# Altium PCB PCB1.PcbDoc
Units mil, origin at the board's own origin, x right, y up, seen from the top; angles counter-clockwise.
Board outline 6000 x 4000 mil, 2 copper layers (Top Layer, Bottom Layer); 38 components, 42 nets, 169 pads, 9 vias.
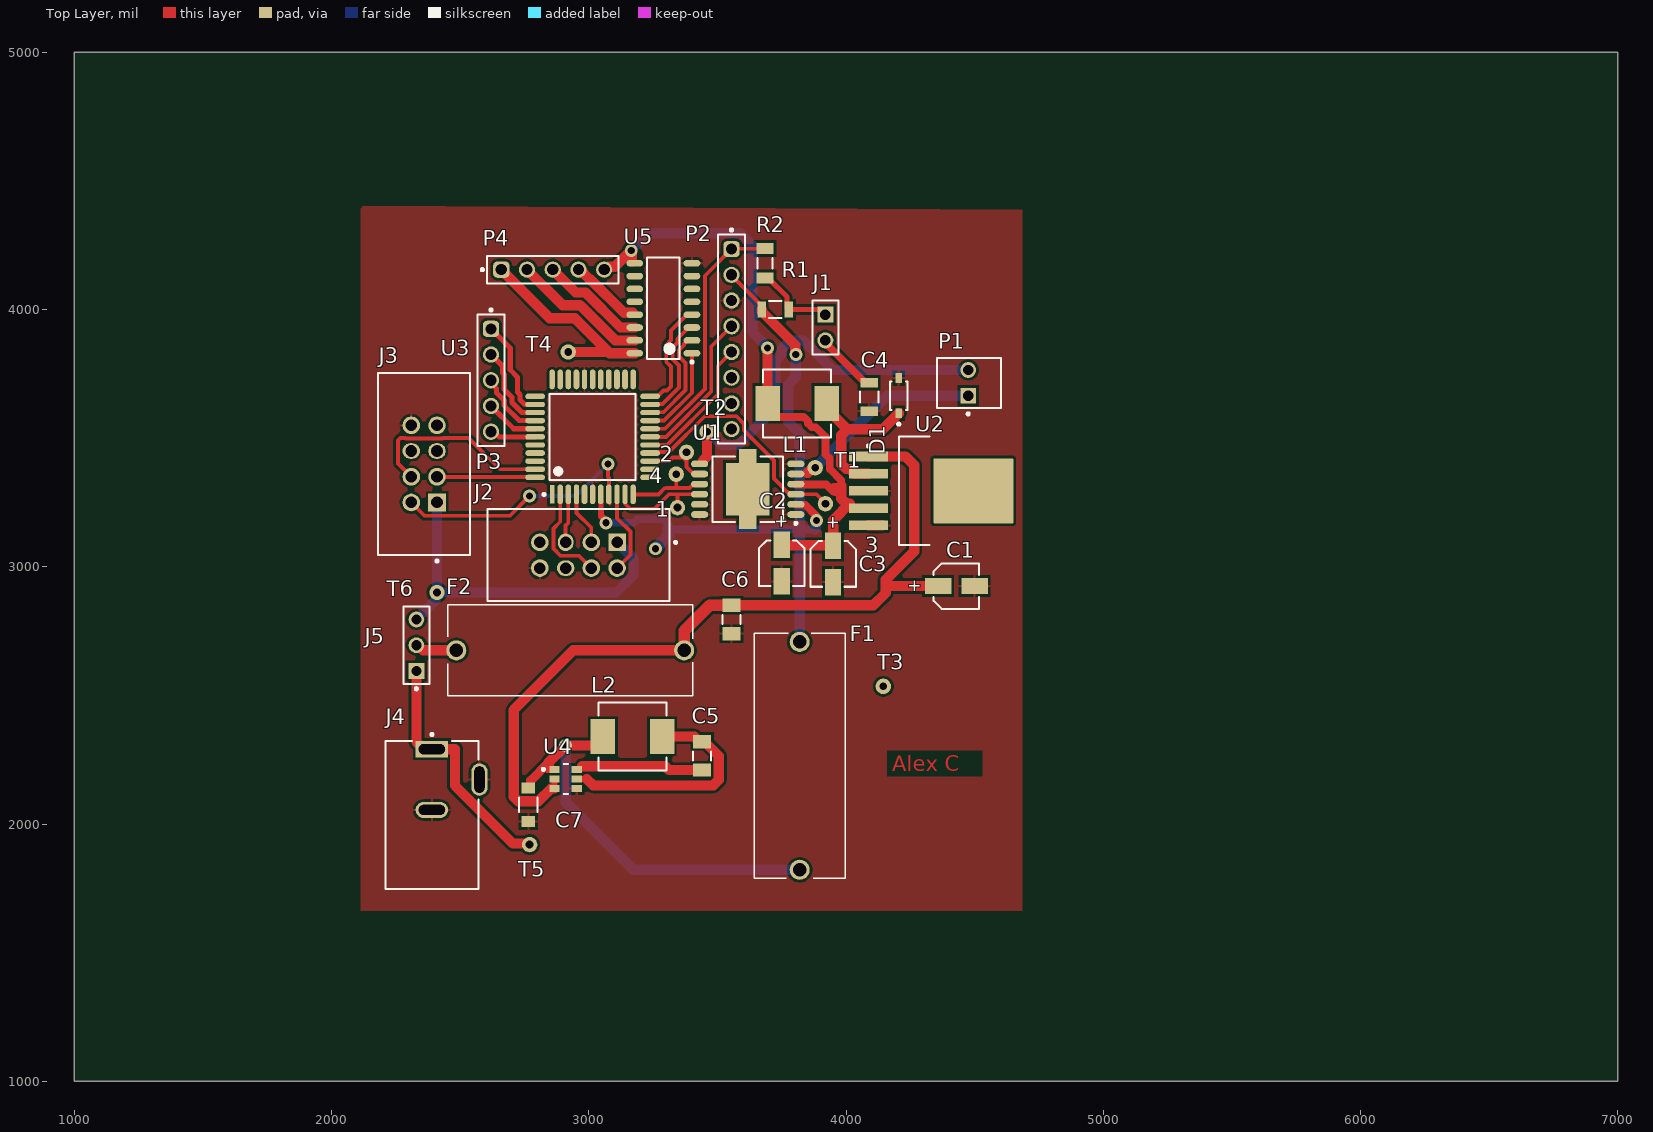
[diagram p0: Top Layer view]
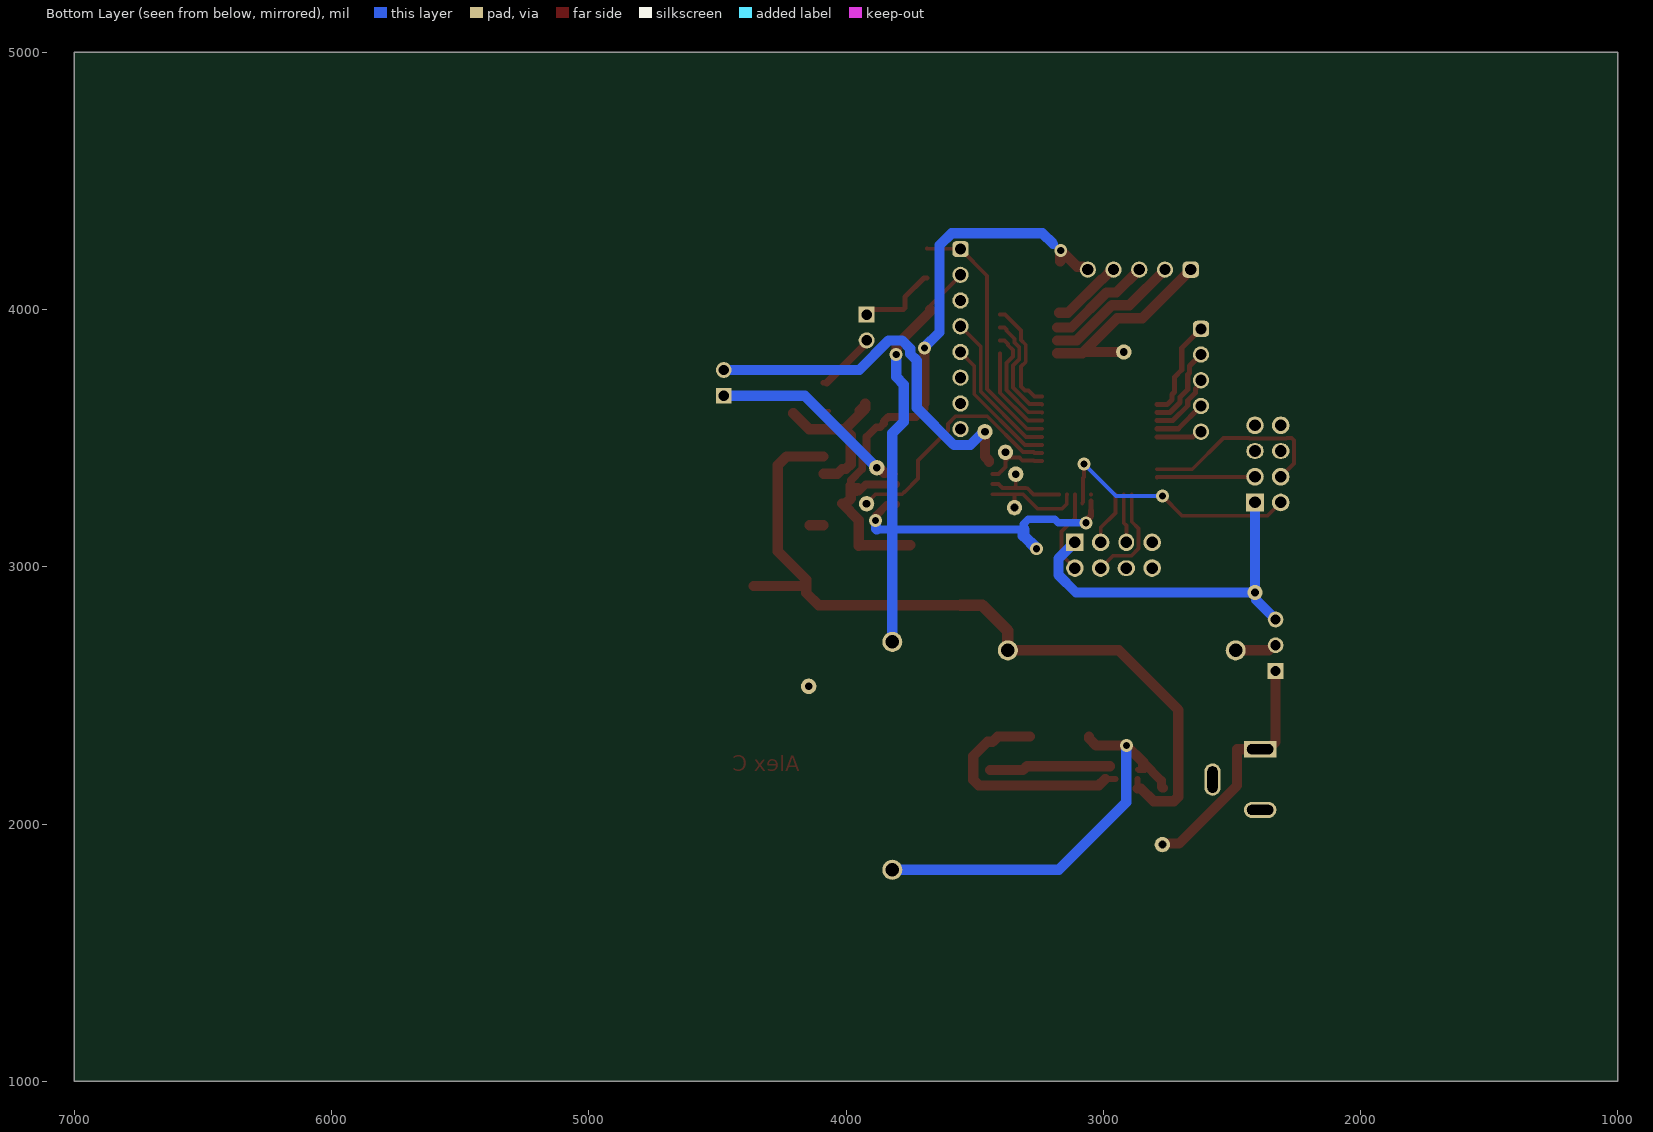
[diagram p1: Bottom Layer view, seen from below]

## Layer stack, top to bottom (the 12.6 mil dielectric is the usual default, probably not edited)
Top Solder: solder mask 0.4, Solder Resist, Dk 3.5
Top Layer: signal copper 1.4
Dielectric 1: dielectric 12.6, FR-4, Dk 4.8
Bottom Layer: signal copper 1.4
Bottom Solder: solder mask 0.4, Solder Resist, Dk 3.5

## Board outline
1000,1000 7000,1000 7000,5000 1000,5000

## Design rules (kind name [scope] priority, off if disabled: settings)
Clearance [All] p1: gap=10 ignorepadtopadclearanceinfootprint=FALSE
HoleSize [All] p1: absolutevalues=TRUE maxlimit=100 minlimit=20 maxpercent=80.000 minpercent=20.000
HoleToHoleClearance [All] p1: gap=17.72 allowstackedmicrovias=TRUE
MinimumAnnularRing [All] p1: minimumring=9.84
MinimumSolderMaskSliver [All] p1: minsoldermaskwidth=7.87
PolygonConnect [All] p1: connectstyle=Relief reliefconductorwidth=10 reliefentries=4 polygonreliefangle="90 Angle" airgapwidth=10
RoutingVias [All] p1: holewidth=28 width=50 viastyle="Through Hole" minholewidth=28 minwidth=50 maxholewidth=28 maxwidth=50
SilkToSilkClearance [All] p1: silktosilkclearance=9
SilkToSolderMaskClearance [IsPad] p1: minsilkscreentomaskgap=5.91 clearancetoexposedcopper=TRUE
SolderMaskExpansion [All] p1: expansion=4 istentingtop=FALSE
SupplyNets "Schematic Supply Nets_3" [InNet('GND')] p1: voltage=0.000
SupplyNets "Schematic Supply Nets_2" [InNet('+5')] p2: voltage=0.000
SupplyNets "Schematic Supply Nets_1" [InNet('+12')] p3: voltage=0.000
SupplyNets "Schematic Supply Nets" [InNet('+3.3')] p4: voltage=0.000
Width [All] p1: maxlimit=50 minlimit=15 preferedwidth=40 minimp=50.000000 maximp=50.000000 favimp=50.000000
25 further rules are at their usual default settings.

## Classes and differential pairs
component class Sheet1: 1 2 3 4 C1 C2 C6 D1 F1 F2 J1 J2 J3 J4 J5 L1 L2 M P4 R1 R2 T1 T2 T3 U1 U2 U3 U4 U5

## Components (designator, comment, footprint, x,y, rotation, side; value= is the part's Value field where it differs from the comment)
1 "Test point" "Test point-Footprint-1" 3345,3230 r90 top
2 "Test point" "Test point-Footprint-1" 3380,3445 r90 top
3 "Test point" "Test point-Footprint-1" 3920,3245 r90 top
4 "Test point" "Test point-Footprint-1" 3340,3360 r90 top
C1 "100uf" WCAP-AS5H_D4H5.5 -45570.87,-47075 r180 top
C2 "300uf" WCAP-AS5H_D4H5.5 -46250,53014.13 r90 top
C3 "100uf" WCAP-AS5H_D4H5.5 -46050,53010.87 r90 top
C4 "0.1uF 25V" FP-C1206C-EB-MFG 4090,3660 r270 top value=100nF
C5 "" FP-1206-L_3_2_0_2-W_1_6_0-IPC_B 3440,2265 r90 top value=100nF
C6 "10uF" FP-1206-L_3_2_0_2-W_1_6_0-IPC_B 3555,2795 r270 top value=100nF
C7 "2x22uF" FP-C3216-160-0_2-MFG 2765,2075 r270 top value=22uF
D1 "1N5819" FP-SOD-123-MFG 4205,3665 r90 top
F1 "4628" FUSE_4628 3820,2265 r90 top
F2 "1.5A" FUSE_4628 2927.91,2675 r0 top
J1 "Conn 01x02" 90120-0762-Footprint-1 3920,3930 r270 top
J2 "Conn 02x04" FP-0702460801-MFG#1 2960,3045 r180 top
J3 "Conn 02x04" FP-0702460801-MFG#2 2360,3400 r90 top
J4 "PJ-102A" FP-PJ-102A-MFG 2390,2035 r180 top
J5 "Conn 01x03" FP-90120-0123-MFG 2330,2695 r90 top
L1 "300 uh" FP-IHLP-2525EZ-FP_2_413x3-MFG 3810,3635 r180 top
L2 "4.7uH" FP-IHLP-2525EZ-FP_2_413x3-MFG 3170,2340 r180 top
P1 "22-23-2021" MOLX-22-23-2021_V 4475,3715 r90 top
P2 "Conn 01x08" 61300811121 3555,3885 r270 top
P3 "BreaKout Headers" 61300511121 2620,3725 r270 top
P4 "Stepper Motor Headers" 61300511121 2860,4155 r0 top
R1 "10k 0.25w" FP-CR1206-IPC_C 3725,4000 r0 top value=10kR
R2 "220 0.25w" RESC3216X60X45NL10T20 3685,4180 r90 top value=220R
T1 "Test point" "Test point-Footprint-1" 3880,3385 r0 top
T2 "Test point" "Test point-Footprint-1" 3460,3525 r0 top
T3 "" "Test point-Footprint-1" 4145,2535 r0 top
T4 "Test point" "Test point-Footprint-1" 2920,3835 r0 top
T5 "Test point" "Test point-Footprint-1" 2770,1920 r90 top
T6 "Test point" "Test point-Footprint-1" 2410,2900 r90 top
U1 "IFX9201SGAUMA1" INF-PG-DSO-12-17_L 3617.99,3301.57 r180 top
U2 "LM2575SX-5.0/NOPB" KTT0005B_L 4331.61,3295 r0 top
U3 "PIC18F47Q10-I/PT" FP-C04-076-IPC_A 3015,3505 r90 top
U4 "AP63203WU-7" FP-TSOT26-MFG 2910,2175 r0 top
U5 "ULN2003D1013TR" STM-SO-16_M 3290,4005 r180 top

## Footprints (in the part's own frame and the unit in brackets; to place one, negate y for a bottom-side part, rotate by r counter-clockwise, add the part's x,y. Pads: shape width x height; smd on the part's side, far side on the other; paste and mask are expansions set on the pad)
90120-0762-Footprint-1 [mm]
  rect 1.57x1.57 hole 1.02 paste-2539.97 mask+0: 1(-1.27,-0.004)
  round 1.57 hole 1.02 paste-2539.97 mask+0: 2(1.27,-0.004)
  silkscreen extent -2.67,-1.27 2.67,1.27, body extent -2.79,-1.44 2.79,1.4, height 0.25
61300511121 [mm] "Pin Header, pitch 2.54 mm, THT, Vertical, single row, 5p"
  rrect50% 1.6x1.6 hole 1.1: 1(-5.08,0)
  round 1.6 hole 1.1: 2(-2.54,0) 3(0,0) 4(2.54,0) 5(5.08,0)
  silkscreen extent -7.07,-1.34 6.5,1.34, body extent -6.35,-1.27 6.35,1.27, height 8.57
61300811121 [mm] "Pin Header, pitch 2.54 mm, THT, Vertical, single row, 8p"
  rrect50% 1.6x1.6 hole 1.1: 1(-8.89,0)
  round 1.6 hole 1.1: 2(-6.35,0) 3(-3.81,0) 4(-1.27,0) 5(1.27,0) 6(3.81,0) 7(6.35,0) 8(8.89,0)
  silkscreen extent -10.88,-1.34 10.31,1.34, body extent -10.16,-1.27 10.16,1.27, height 8.57
FP-1206-L_3_2_0_2-W_1_6_0-IPC_B [mil]
  rect 51.36x71.11 smd paste+0 mask+0: 1(-55.15,0) 2(55.15,0)
  silkscreen extent -18,-36 18,36, body extent -91,-45 91,45, height 10
FP-90120-0123-MFG [mm]
  rect 1.55x1.55 hole 1 paste-2539.97 mask+0: 1(-2.54,0)
  round 1.55 hole 1 paste-2539.97 mask+0: 2(0,0) 3(2.54,0)
  silkscreen extent -4.42,-1.27 3.81,1.27, body extent -3.91,-1.37 3.91,1.37, height 0.25
FP-0702460801-MFG#1 [mm]
  rect 1.74x1.74 hole 1.14 paste-2539.97 mask+0: 1(-3.81,-1.27)
  round 1.74 hole 1.14 paste-2539.97 mask+0: 2(-3.81,1.27) 3(-1.27,-1.27) 4(-1.27,1.27) 7(3.81,-1.27) 8(3.81,1.27)
  oval 1.537x1.74 hole 1.14 paste-2539.97 mask+0: 5(1.27,-1.27)
  oval 1.74x1.537 hole 1.14 paste-2539.97 mask+0: 6(1.27,1.27)
  silkscreen extent -9.72,-4.54 8.99,4.54, body extent -9.09,-4.64 9.09,4.64, height 0.25
FP-0702460801-MFG#2 [mm]
  rect 1.74x1.74 hole 1.14 paste-2539.97 mask+0: 1(-3.81,-1.27)
  round 1.74 hole 1.14 paste-2539.97 mask+0: 2(-3.81,1.27) 3(-1.27,-1.27) 4(-1.27,1.27) 7(3.81,-1.27) 8(3.81,1.27)
  oval 1.537x1.74 hole 1.14 paste-2539.97 mask+0: 5(1.27,-1.27) 6(1.27,1.27)
  silkscreen extent -9.71,-4.54 8.99,4.54, body extent -9.09,-4.64 9.09,4.64, height 0.25
FP-C04-076-IPC_A [mm]
  rect 1.803x0.464 smd paste+0 mask+0: 1(-5.675,4)
  rrect100% 1.955x0.526 smd paste+0 mask+0: 2(-5.675,3.2) 3(-5.675,2.4) 4(-5.675,1.6) 6(-5.675,0) 7(-5.675,-0.8) 8(-5.675,-1.6) 9(-5.675,-2.4) 10(-5.675,-3.2) 11(-5.675,-4) 27(5.675,-0.8) 29(5.675,0.8) 31(5.675,2.4) 33(5.675,4)
  rrect100% 1.955x0.566 smd paste+0 mask+0: 5(-5.675,0.8) 23(5.675,-4) 24(5.675,-3.2) 25(5.675,-2.4) 26(5.675,-1.6) 28(5.675,0) 30(5.675,1.6)
  rrect100% 0.566x1.955 smd paste+0 mask+0: 12(-4,-5.675) 13(-3.2,-5.675) 15(-1.6,-5.675) 17(0,-5.675) 22(4,-5.675) 34(4,5.675) 39(0,5.675) 41(-1.6,5.675) 43(-3.2,5.675)
  rrect100% 0.526x1.955 smd paste+0 mask+0: 14(-2.4,-5.675) 16(-0.8,-5.675) 18(0.8,-5.675) 19(1.6,-5.675) 20(2.4,-5.675) 21(3.2,-5.675) 35(3.2,5.675) 36(2.4,5.675) 37(1.6,5.675) 38(0.8,5.675) 40(-0.8,5.675) 42(-2.4,5.675) 44(-4,5.675)
  rrect100% 1.953x0.526 smd paste+0 mask+0: 32(5.675,3.2)
  silkscreen extent -5.8,-4.25 4.25,4.92, body extent -7.15,-7.15 7.15,7.15, height 0.25
FP-C1206C-EB-MFG [mm]
  rect 0.95x1.7 smd paste+0 mask+0: 1(-1.4,0) 2(1.4,0)
  silkscreen extent -0.55,-0.9 0.55,0.9, body extent -2,-1 2,1, height 0.25
FP-C3216-160-0_2-MFG [mm]
  rect 1.1x1.35 smd paste+0 mask+0: 1(-1.65,0) 2(1.65,0)
  silkscreen extent -0.72,-0.9 0.72,0.9, body extent -2.3,-1 2.3,1, height 0.25
FP-CR1206-IPC_C [mil]
  rect 33.79x61.5 smd paste+0 mask+0: 1(-52.24,0) 2(52.24,0)
  silkscreen extent -24,-32 24,32, body extent -73,-36 73,36, height 10
FP-IHLP-2525EZ-FP_2_413x3-MFG [mil]
  rect 95x135 smd paste+0 mask+0: 1(-115,0) 2(115,0)
  silkscreen extent -132,-132 132,132, body extent -166,-136 166,136, height 10
FP-PJ-102A-MFG [mm]
  rect 3.2x1.6 hole 1 slot 2.6 at 0 deg paste-2539.97 mask+0: 1(0,-6.5)
  rrect100% 3.2x1.6 hole 1 slot 2.6 at 0 deg paste-2539.97 mask+0: 2(0,-0.5)
  rrect100% 1.6x3.2 hole 2.6 slot 1 at 0 deg paste-2539.97 mask+0: 3(-4.7,-3.5)
  silkscreen extent -4.6,-8.07 4.6,7.3, body extent -5.6,-7.4 4.7,7.4, height 0.25
FP-SOD-123-MFG [mm]
  rect 0.97x0.65 smd paste+0 mask+0: 1(-1.74,0) 2(1.74,0)
  silkscreen extent -2.92,-0.85 1.42,0.85, body extent -2.32,-0.95 2.32,0.95, height 0.25
FP-TSOT26-MFG [mm]
  rect 1x0.7 smd paste+0 mask+0: 1(-1.099,0.95) 3(-1.099,-0.95) 4(1.099,-0.95) 6(1.099,0.95)
  rect 1x0.687 smd paste+0 mask+0: 2(-1.099,0) 5(1.099,0)
  silkscreen extent -2.32,-1.5 0.22,1.5, body extent -1.7,-1.6 1.7,1.6, height 0.25
FUSE_4628 [mm]
  round 1.98 hole 1.32: 1(-11.25,0) 2(11.25,0)
  silkscreen extent -12.1,-4.49 12.1,4.49, body extent -12.1,-4.5 12.1,4.5, height 11.99
INF-PG-DSO-12-17_L [mm] "SOP, 12-Leads, Body 7.6x6.5mm, Pitch 1mm, Thermal Pad 7.9x4.3mm, IPC High Density"
  oval 1.7x0.65 smd: 1(-4.75,2.5) 2(-4.75,1.5) 3(-4.75,0.5) 4(-4.75,-0.5) 5(-4.75,-1.5) 6(-4.75,-2.5) 7(4.75,-2.5) 8(4.75,-1.5) 9(4.75,-0.5) 10(4.75,0.5) 11(4.75,1.5) 12(4.75,2.5)
  rect 4.3x5.2 smd: 13(0,0)
  rect 1.7x1.35 smd: ""(0,3.275) ""(0,-3.275)
  silkscreen extent -4.88,-3.25 3.5,3.5, body extent -3.8,-3.25 3.8,3.25, height 2.6
KTT0005B_L [mm] "DPAK, 5-Leads, Body 10.65x9.65mm, Pitch 1.7mm, IPC High Density"
  rrect11% 3.85x0.95 smd: 1(-6.2,3.4) 2(-6.2,1.7) 3(-6.2,0) 4(-6.2,-1.7) 5(-6.2,-3.4)
  rrect2% 7.9x6.4 smd: 6(4.15,0)
  silkscreen extent -6.32,-5.35 -0.2,5.35, body extent -3.2,-5.32 6.45,5.33, height 4.83
MOLX-22-23-2021_V [mm] "THD, 2-Leads, Body 6.35x4.93mm, Pitch 2.54mm"
  rect 1.55x1.55 hole 1.02: 1(-1.27,0)
  round 1.55 hole 1.02: 2(1.27,0)
  silkscreen extent -3.19,-3.25 2.46,3.1, body extent -2.46,-3.25 2.46,3.1, height 10.66
RESC3216X60X45NL10T20 [mm] "Chip Resistor, 2-Leads, Body 3.20x1.60mm, IPC Medium Density"
  rect 1.1x1.7 smd: 1(-1.45,0) 2(1.45,0)
  silkscreen extent -0.5,-0.75 0.5,0.75, body extent -1.65,-0.85 1.65,0.85, height 0.6
STM-SO-16_M [mm] "SOIC, 16-Leads, Body 10x4mm, Pitch 1.27mm, IPC Low Density"
  oval 1.65x0.65 smd: 1(-2.825,4.445) 2(-2.825,3.175) 3(-2.825,1.905) 4(-2.825,0.635) 5(-2.825,-0.635) 6(-2.825,-1.905) 7(-2.825,-3.175) 8(-2.825,-4.445) 9(2.825,-4.445) 10(2.825,-3.175) 11(2.825,-1.905) 12(2.825,-0.635) 13(2.825,0.635) 14(2.825,1.905) 15(2.825,3.175) 16(2.825,4.445)
  silkscreen extent -2.95,-5 1.6,5.44, body extent -2,-5 2,5, height 1.75
"Test point-Footprint-1" [mil]
  round 60 hole 30: 1(0,0)
WCAP-AS5H_D4H5.5 [mm] "Aluminum Electrolytic Capacitors, 4x5.5mm"
  rect 2.6x1.6 smd: 1(-1268.2,-1270) 2(-1271.8,-1270)
  silkscreen extent -1272.25,-1272.25 -1267.75,-1267.75, body extent -1272.5,-1272.15 -1267.5,-1267.85, height 5.5

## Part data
1 2 3 4 T1 T2 T4 T5 T6: library part CMP-00030-4, "tht test point"
C1 C2 C3: library part CMP-00009-1, "WCAP-AS5H Aluminum Electrolytic Capacitors"
C4: library part CMP-00015-1, "Ceramic Capacitor, Multilayer, Ceramic, 25V, 10% +Tol, 10% -Tol, X7R, 15% TC, 0.1uF, Surface Mount, 1206", Capacitor Type=Ceramic, Case/Package=1206, Max Operating Temperature=125°C, Min Operating Temperature=-55°C, Package Shape=Rectangular, Package Style=SMTMeter, Rated DC Voltage (URdc)=25V, Temperature Characteristics Code=X7R, Tolerance  (fill in as +-)=10%
C5 C6: library part CMP-00010-1, "Ceramic Capacitor, Multilayer, Ceramic, 100V, 10% +Tol, 10% -Tol, X7R, 15% TC, 0.1uF, Surface Mount, 1206", Capacitor Type=Ceramic, Case/Package=1206, Max Operating Temperature=125°C, Min Operating Temperature=-55°C, Package Shape=Rectangular, Package Style=SMTMeter, Rated DC Voltage (URdc)=100V, Temperature Characteristics Code=X7R, Tolerance  (fill in as +-)=10%
C7: library part CMP-00013-1, "Ceramic Capacitor, Multilayer, Ceramic, 35V, 20% +Tol, 20% -Tol, X5R, 15% TC, 22uF, Surface Mount, 1206", Capacitor Type=Ceramic, Case/Package=1206, Max Operating Temperature=85°C, Min Operating Temperature=-55°C, Package Shape=Rectangular, Package Style=SMTMeter, Rated DC Voltage (URdc)=35V, Temperature Characteristics Code=X5R, Tolerance  (fill in as +-)=20%
D1: library part CMP-00040-1, "Rectifier Diode, Schottky, 1 Phase, 1 Element, 0.5A, 60V V(RRM), Silicon", Forward Voltage=660mV, Max Operating Temperature=150°C, Max Output current=500mA, Non-rep Pk Forward Current-Max=5.5A, Package Body Material=Plastic, Package Shape=Rectangular, Package Style="SMALL OUTLINEMeter", Peak Reflow Temperature (Cel)=260°C, Rep Pk Reverse Voltage-Max=60V, Time @ Peak Reflow Temperature-Max (s)=30s
F1 F2: library part CMP-006-000000-1, "5mm Slim Line Fuse holder", Package=None
J1: library part CMP-00026-1, "Board Connector, 2 Contact(s), 1 Row(s), Male, Straight, 0.1 inch Pitch, Solder Terminal, Locking, Black Insulator, Receptacle", Contact Resistance=20mR, Dielectric Withstanding Voltage (DC)=1kV, Flammability Rating="UL94 V-0", Insulation Color=Black, Insulation Resistance=5GR, Max Operating Temperature=125°C, Min Operating Temperature=-55°C, Rated Current (Signal)=3A
J2 J3: library part CMP-00034-1, "Board Connector, 8 Contact(s), 2 Row(s), Male, Straight, 0.1 inch Pitch, Solder Terminal, Guide Slot, Black Insulator, Receptacle", Dielectric Withstanding Voltage (AC)=900V, Flammability Rating="UL94 V-0", Insulation Color=Black, Insulation Resistance=12GR, Manufacturer Series=70246, Max Operating Temperature=120°C, Min Operating Temperature=-55°C, Rated Current (Signal)=2.5A
J4: library part CMP-00031-1, "2.0 x 6.5 mm, 2.5 A, Horizontal, Through Hole, Tapered Pins, Dc Power Jack Connector"
J5: library part CMP-00025-1, "Board Connector, 3 Contact(s), 1 Row(s), Male, Straight, 0.1 inch Pitch, Solder Terminal, Black Insulator, Receptacle", Contact Resistance=20mR, Dielectric Withstanding Voltage (DC)=350V, Flammability Rating="UL94 V-0", Insulation Color=Black, Insulation Resistance=5GR, Max Operating Temperature=125°C, Min Operating Temperature=-55°C, Rated Current (Signal)=3A
L1: library part CMP-00011-1, "General Purpose Inductor, 4.7uH, 20%, 1 Element, Composite-Core, SMD, 2525", Case/Size Code=2726, DC Resistance (DCR)=30.3mR, Inductance-Nom (L)=4.7uH, Inductor Application="HIGH CURRENT INDUCTOR", Inductor Type="GENERAL PURPOSE INDUCTOR", Max Current Rating=6.5A, Max Operating Temperature=125°C, Min Operating Temperature=-55°C, Package Height=5mm, Package Length=6.86mm, Package Style=SMTMeter, Package Width=6.47mm, Test Frequency=100kHz, Tolerance=20%
L2: library part CMP-00011-1, "General Purpose Inductor, 4.7uH, 20%, 1 Element, Composite-Core, SMD, 2525", Case/Size Code=2726, DC Resistance (DCR)=30.3mR, Inductor Application="HIGH CURRENT INDUCTOR", Inductor Type="GENERAL PURPOSE INDUCTOR", Max Current Rating=6.5A, Max Operating Temperature=125°C, Min Operating Temperature=-55°C, Package Height=5mm, Package Length=6.86mm, Package Style=SMTMeter, Package Width=6.47mm, Test Frequency=100kHz, Tolerance=20%
P1: library part CMP-1704-00001-3, "Male Header, Pitch 2.54 mm, 1 x 2 Position, Height 10.67 mm, Tail Length 3.56 mm, 0 to 75 degC, RoHS, Bulk", Max Operating Temperature="75 degC", Min Operating Temperature="0 degC", Package Quantity=3000
P2: library part CMP-00017-1, "Board Connector, 8 Contact(s), 1 Row(s), Male, Straight, 0.1 inch Pitch, Solder Terminal, Locking, Black Insulator, Plug", Contact Resistance=20mR, Dielectric Withstanding Voltage (AC)=500V, Insulation Color=Black, Insulation Resistance=1GR, Manufacturer Series=613, Max Operating Temperature=125°C, Min Operating Temperature=-40°C, Rated Current (Signal)=3A
P3 P4: library part CMP-1502-01068-3, Color=Black, Contact Resistance=20mΩ, Current Rating=3A, Max Operating Temperature=105°C, Min Operating Temperature=-40°C, Operating Supply Voltage=250V
R1: library part CMP-00022-1, "Fixed Resistor, Metal Glaze/thick Film, 0.25W, 10000ohm, 200V, 5% +/-Tol, 200ppm/Cel, Surface Mount, 1206", Case/Package=1206, Max Operating Temperature=155°C, Min Operating Temperature=-55°C, Package Height=0.6mm, Package Length=3.2mm, Package Shape=Rectangular, Package Width=1.6mm, Power=250mW, Rated Temperature=70°C, Resistor Type="FIXED RESISTOR", Temperature Coefficient (ppm/Cel)=200, Tolerance=5%, Working Voltage=200V
R2: library part CMP-00024-1, "Fixed Resistor, Metal Glaze/thick Film, 0.25W, 220ohm, 200V, 1% +/-Tol, 100ppm/Cel, Surface Mount, 1206", Case/Package=1206, Max Operating Temperature=155°C, Min Operating Temperature=-55°C, Package Height=0.55mm, Package Length=3.2mm, Package Shape=Rectangular, Package Width=1.6mm, Power=250mW, Rated Temperature=70°C, Resistor Type="FIXED RESISTOR", Temperature Coefficient (ppm/Cel)=100, Tolerance=1%, Working Voltage=200V
T3: library part CMP-00030-3, "tht test point"
U1: library part CMP-1645-00001-1, "6 A H-Bridge with SPI, 0.1 Ohm, -40 to 125 degC, 12-Pin PG-DSO-12-17, RoHS, Tape and Reel", Generic Part Number=IFX9201SG, Temperature Max="125 degC", Temperature Min="-40 degC"
U2: library part CMP-0069-00083-3, "SIMPLE SWITCHER® 1A Step-Down Voltage Regulator, 5-pin TO-263, Pb-Free", Manufacturer="Texas Instruments", PackageTopMarking="NSUZXYTTE#*LM2575S*-5.0 P+", PowerWise=N
U3: library part CMP-00000-1, "RISC Microcontroller, 8-Bit, FLASH, PIC18 CPU, 64MHz, CMOS, PQFP44"
U4: library part CMP-00004-1, "Switching Regulator"
U5: library part CMP-2000-05374-1, "Seven NPN Darlington Array Transistor, 50 V, 500 mA, -40 to 85 degC, 8-Pin SOIC, RoHS, Tape and Reel", Collector Emitter Voltage V(br)ceo=50V, DC Collector Current=500mA, DC Current Gain hFE=1000hFE, Manufacturer=STMicroelectronics, Operating Temperature Max=85degC, Package Description="16-Pin Small Outline Integrated Circuit, Body 9.9 x 3.9 mm, Pitch 1.27 mm", Package Reference=SO-16, Power Dissipation Pd=-, Transistor Case Style=SOIC

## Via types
v1: diameter 50, hole 28, Top Layer to Bottom Layer, 9 vias

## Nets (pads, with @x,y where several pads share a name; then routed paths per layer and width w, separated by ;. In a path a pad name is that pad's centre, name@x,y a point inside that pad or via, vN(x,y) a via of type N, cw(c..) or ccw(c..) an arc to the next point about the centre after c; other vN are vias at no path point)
+3.3: F1.2 P2.2 R1.1 U1.2 U3.7 | length 2732.6
  Top Layer w15: U3.7 U3.7@3047.59,3280.47 ; P2.2 3555,4131.61 3672.76,4013.86 R1.1
  Top Layer w20: 3047.59,3217.41 U3.7@3047.59,3255.57
  Top Layer w25: 3047.59,3217.41 3047.59,3197.31 3067.39,3177.51 v1(3067.39,3170.74)
  Top Layer w30: U1.2 3806.57,3240.94 3841.32,3240.94 3881.17,3201.09 3881.17,3183.83 v1(3885,3180)
  Top Layer w40: R1.1 3672.76,3992.36 3803.09,3862.03 3803.09,3826.91 v1(3805,3825)
  Top Layer w45: v1@3260,3068.65 v1(3260,3070)
  Bottom Layer w30: v1(3067.39,3170.74) 3175.02,3170.74 3188.53,3184.25 3290.75,3184.25 3310,3165 ; 3310,3145 3820,3145 3880,3145
  Bottom Layer w40: v1(3805,3825) 3805,3737.97 3775,3707.97 3775,3563.65 3820,3518.65 3820,3145 F1.2 ; 3880,3145 3883.09,3148.09 3883.09,3178.09 v1(3885,3180)
  Bottom Layer w45: v1(3260,3070) 3260,3071.35 3310,3121.35 3310,3145
+5: C2.1 C3.1 L1.2 P4.5 U1.4 U2.4 U5.9 | length 2479.3
  Top Layer w30: L1.2 3695,3615 3727.5,3582.5 3834.93,3582.5 3852.5,3564.93 3852.5,3557.14 3867.14,3542.5 3882.5,3542.5 3920,3505 3920,3437.78 3936.73,3421.05 3936.73,3380.3 3981.87,3335.16 3981.87,3315.7 3981.73,3315.56 ; U1.4 3806.57,3319.69 3923.1,3319.69 3950,3292.78 3955,3292.78
  Top Layer w40: P4.5 3066.22,4155 3077.72,4166.5 3101.5,4166.5 v1(3165,4230) 3165,4227.29 3166.94,4225.35 U5.9@3166.94,4187.2 ; L1.2 v1@3695,3835 ; C2.1 3751.63,3083.37 3948.37,3083.37 C3.1 3950,3181.5 4014.8,3246.3 4000.51,3246.3 3981.73,3265.08 3981.73,3315.56 ; 3960,3294.85 3953.22,3301.63 3953.22,3305 3981.73,3305
  Bottom Layer w40: 3195,4255 3236.5,4296.5 3589.7,4296.5 3636.52,4249.68 3636.52,3911.19 3695,3852.71 v1(3695,3850)
+12: C1.1 C6.1 F2.2 U2.1 U4.2 U4.3 | length 3178.2
  Top Layer w25: U4.3 U4.2
  Top Layer w40: U4.3 2853.29,2137.6 2804,2088.31 2726,2088.31 2708.43,2105.88 2708.43,2443.43 2940,2675 F2.2 ; C6.1 4106.57,2850.15 4154.41,2897.99 4154.41,2924.11 ; U2.1 4231.14,3428.86 4265,3395 4265,3060.81 4154.41,2950.22 4154.41,2924.11 ; C1.1 4155.3,2925 4154.41,2924.11
  Top Layer w45: F2.2 3370.83,2750.83 3470.15,2850.15 C6.1
CON_PWR: J2.1 J3.1 J5.3 T6.1 | length 1438.3
  Top Layer w45: J5.3 J5.3@2330,2799.34
  Bottom Layer w40: J5.3 2406.17,2871.17 2406.17,2896.17 T6.1 ; J3.1 T6.1 ; J2.1 3174.25,3030.75 3174.25,2968.39 3105.87,2900 T6.1
GND: C1.2 C2.2 C3.2 C4.2 C6.2 C7.2 D1.2 J2.8 J3.8 J4.2 J4.3 P2.3 U1.1 U1.6 U1.11 U1.12 U2.3 U2.5 U3.6 U3.29 U4.4 U5.8 | length 78.5
  Top Layer w15: C4.2@4066,3604.88 C4.2
  Top Layer w40: U2.5 U2.5@4142.01,3161.14
GPIO_IN_1: J2.3 U3.4 | length 210.6
  Top Layer w15: U3.4 2952.01,3209.67 3009.93,3151.75 3009.93,3095.07 J2.3
GPIO_IN_2: J2.5 U3.3 | length 190.9
  Top Layer w15: J2.5 2910,3160.56 2920.51,3171.07 U3.3
GPIO_OUT_1: J2.4 U3.2 | length 400.7
  Top Layer w15: U3.2 2889.02,3174.93 2862.25,3148.16 2862.25,3071.22 2890.72,3042.75 2962.25,3042.75 J2.4
GPIO_OUT_2: J3.3 U3.44 | length 382.6
  Top Layer w15: J3.3 2411.39,3348.61 2790.47,3348.61 U3.44
GPIO_OUT_3: J3.4 U3.43 | length 751.2
  Top Layer w15: J3.4 2258.25,3401.75 2258.25,3491.21 2267.03,3500 2286.81,3500 2288.56,3498.25 2431.44,3498.25 2433.19,3500 2533.19,3500 2654.17,3379.02 U3.43
ICSPCLK: P2.5 U3.16 | length 531.1
  Top Layer w15: U3.16 3304.21,3473.5 3501.2,3670.49 3501.2,3781.2 P2.5
ICSPDAT: P2.4 U3.17 | length 597.4
  Top Layer w15: U3.17 3300.36,3505 3476.2,3680.84 3476.2,3856.2 P2.4
MCLR/RESET: P2.1 R2.2 U3.18 | length 994.5
  Top Layer w15: U3.18 3296.5,3536.5 3451.2,3691.2 3451.2,4131.2 P2.1 3556.04,4236.04 3683.96,4236.04 R2.2
NetC4_1: C4.1 J1.2 | length 244
  Top Layer w20: J1.2@3919.84,3870.51 J1.2 ; C4.1@4075.24,3715.12 C4.1
  Top Layer w30: J1.2@3919.84,3870.51 C4.1@4075.24,3715.12
NetC5_1: C5.1 U4.6 | length 471.3
  Top Layer w40: 2975,2225 3296.57,2225 3311.72,2209.85 C5.1
NetC5_2: C5.2 L2.1 U4.5 | length 916.2
  Top Layer w25: U4.5 2991.78,2175
  Top Layer w40: 2991.78,2175 3016.78,2150 3483.81,2150 3505.56,2171.74 3505.56,2264.47 3449.87,2320.15 C5.2 3430.13,2320.15 3410.28,2340 L2.1
NetC7_1: C7.1 F1.1 L2.2 U4.1 | length 1675.5
  Top Layer w20: 2838.58,2208.62 2862.93,2208.62 U4.1
  Top Layer w35: C7.1 2769.92,2139.96 2774.07,2144.11 2774.07,2169.07 2845,2240
  Top Layer w40: 2845,2225 2845,2240 v1(2910,2305) 3027.5,2305 3055,2332.5 L2.2
  Bottom Layer w40: v1(2910,2305) 2910,2085 3172.91,1822.09 F1.1
NetD1_1: D1.1 L1.1 U2.2 | length 664.1
  Top Layer w30: L1.1 L1.1@3952.32,3607.68
  Top Layer w40: L1.1 3925,3615 4005,3535 ; U2.2 4033.03,3361.93 4014.8,3380.16 4000.51,3380.16 3981.73,3398.94 3981.73,3511.73 4005,3535 ; D1.1 4143.5,3535 4005,3535
NetF2_1: F2.1 J5.2 | length 163.3
  Top Layer w40: J5.2 2335.69,2695 2355.69,2675 F2.1
NetJ1_1: J1.1 R1.2 R2.1 | length 318.9
  Top Layer w20: R2.1 3696.81,4122.91 3770.35,4049.37 3770.35,4006.89 R1.2 3899.84,4000 J1.1
NetJ4_1: J4.1 J5.1 T5.1 | length 968.9
  Top Layer w40: J5.1 2330,2319.41 2358.5,2290.91 J4.1 2480,2290.91 2480,2149.37 2705.54,1923.83 2766.17,1923.83 T5.1 T5.1@2770,1924.95
NetM1_1: P1.1 T1.1 U1.5 | length 796.7
  Top Layer w15: U1.5 3846.82,3360.63 3849.84,3363.65 3849.84,3364.69
  Top Layer w40: 3849.84,3364.69 3850.88,3364.69 3861.19,3375 3864.59,3375 3874.59,3385 T1.1
  Bottom Layer w40: T1.1 4160,3665 P1.1
NetM1_2: P1.2 T2.1 U1.7 | length 1496.5
  Top Layer w40: U1.7@3444.45,3407.2 3444.45,3413.46 3460,3429.02 T2.1
  Bottom Layer w40: T2.1 3465.41,3525 3516.91,3473.5 3580.47,3473.5 3725,3618.03 3725,3802.22 3750,3827.22 3750,3847.78 3782.22,3880 3833.71,3880 3948.71,3765 P1.2
NetP3_1: P3.1 U3.35 | length 388.4
  Top Layer w20: P3.1 2694.74,3850.26 2694.74,3765.51 2723.14,3737.12 2723.14,3679.54 2733.07,3669.61 2733.07,3649.58 2751.53,3631.12 2791.42,3631.12 U3.35
NetP3_2: P3.2 U3.36 | length 326.3
  Top Layer w20: P3.2 2664.74,3780.26 2664.74,3753.09 2671.5,3746.33 2671.5,3688.76 2701.5,3658.76 2701.5,3638.73 2740.6,3599.62 2791.42,3599.62 U3.36
NetP3_3: P3.3 U3.37 | length 264.2
  Top Layer w20: P3.3 2620,3713.37 2641.5,3691.87 2641.5,3676.33 2671.5,3646.33 2671.5,3626.3 2729.67,3568.13 2791.42,3568.13 U3.37
NetP3_4: P3.4 U3.38 | length 208.2
  Top Layer w20: P3.4 2708.5,3536.5 U3.38
NetP3_5: P3.5 U3.39 | length 179.8
  Top Layer w20: P3.5 2631.63,3525 2651.63,3505 U3.39
NetP4_1: P4.1 T4.1 U5.16 | length 835
  Top Layer w15: P4.1 P4.1@2672.44,4142.56
  Top Layer w40: P4.1 2848.5,3966.5 2945.47,3966.5 3081.97,3830 ; T4.1 3076.97,3835 3081.97,3830 ; U5.16 3081.97,3830
NetP4_2: P4.2 U5.15 | length 545.7
  Top Layer w15: P4.2 P4.2@2772.99,4155
  Top Layer w40: P4.2 2898.5,4016.5 2966.18,4016.5 3102.68,3880 U5.15
NetP4_3: P4.3 U5.14 | length 412
  Top Layer w40: P4.3 2948.5,4066.5 2986.89,4066.5 3123.39,3930 U5.14
NetP4_4: P4.4 U5.13 | length 281.1
  Top Layer w40: P4.4 2966.22,4155 3004.73,4116.5 3007.6,4116.5 3136.9,3987.2 U5.13@3171.58,3987.2
RA0: U3.19 U5.1 | length 361.2
  Top Layer w15: U3.19 3292.64,3567.99 3401.22,3676.58 U5.1
RA1: U3.20 U5.2 | length 408
  Top Layer w15: U3.20 3239.53,3600.58 3289.87,3600.58 3376.22,3686.93 3376.22,3792.47 3351.24,3817.45 3351.24,3842.55 3370,3861.31 3370,3865.6 3384.4,3880 U5.2
RA2: U3.21 U5.3 | length 424.2
  Top Layer w15: U3.21 3239.53,3632.07 3286.01,3632.07 3351.22,3697.29 3351.22,3782.12 3326.24,3807.1 3326.24,3852.9 3345,3871.66 3345,3886.31 3376.24,3917.55 3376.24,3921.84 3384.4,3930 U5.3
RA3: U3.22 U5.4 | length 437
  Top Layer w15: U3.22 3267.76,3662.48 3290.37,3685.09 3303.66,3685.09 3320,3701.42 3320,3777.98 3301.24,3796.74 3301.24,3863.26 3320,3882.02 3320,3918.47 3381.53,3980 U5.4
RB2: 3.1 U1.3 U3.15 | length 908.9
  Top Layer w15: U3.15 3267.76,3442.01 3271.41,3445.65 3311.72,3445.65 3451.07,3585 3574.29,3585 3604,3555.29 3604,3529.3 3720.14,3413.15 3720.14,3342.61 3771.78,3290.96 3772.39,3290.96 3781.46,3281.89 3885.61,3281.89 3900,3267.5
RB3: 2.1 U1.8 U3.14 | length 239.2
  Top Layer w15: U3.14 3268.13,3410.51 3270.98,3413.37 3314.79,3413.37 3326.19,3424.77 3366.84,3424.77 3380.02,3411.59 3380.02,3387.45 3397.77,3369.7 3398.37,3369.7 3407.45,3360.63 U1.8
RB4: 1.1 U1.10 U3.10 | length 409.5
  Top Layer w15: U3.10 3142.07,3280.47 3142.07,3244.44 3160.94,3225.57 3255.02,3225.57 3311.34,3281.89 3345,3281.89 ; 1.1 3345,3281.89 ; U1.10 3345,3281.89
RB5: 4.1 U1.9 U3.11 | length 330.8
  Top Layer w15: U3.11 3271.43,3281.56 3294.87,3305 3299.1,3305 3300.99,3306.89 3346.73,3306.89 ; 4.1 3340,3313.62 3346.73,3306.89 ; U1.9 3407.45,3321.26 3398.37,3312.19 3397.77,3312.19 3392.47,3306.89 3346.73,3306.89
UART_RX: J2.2 U3.9 | length 329.6
  Top Layer w15: U3.9 3109.49,3188.76 3161.75,3136.5 3161.75,3046.75 J2.2
UART_TX: J3.2 U3.8 | length 1027
  Top Layer w15: J3.2 2361.75,3198.25 2693.25,3198.25 v1(2770,3275) ; v1(3075,3400) 3075,3349.03 3077.99,3346.04 U3.8 3077.99,3251.87 3081.64,3248.23 U3.8@3081.64,3245.74
  Bottom Layer w15: v1(2770,3275) 2950,3275 v1(3075,3400)
pads on no net: J2.6 J2.7 J3.5 J3.6 J3.7 P2.6 P2.7 P2.8 T3.1 U1. U1.13 U2.6 U3.1 U3.5 U3.12 U3.13 U3.23 U3.24 U3.25 U3.26 U3.27 U3.28 U3.30 U3.31 U3.32 U3.33 U3.34 U3.40 U3.41 U3.42 U5.5 U5.6 U5.7 U5.10 U5.11 U5.12

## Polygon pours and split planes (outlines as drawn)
GND on Top Layer "GND_L01_P001" (solid, pour order 1): 2113.28,4403.28 2113.28,1663.28 4685,1663.28 4685,4388.07

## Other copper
Top Layer:
  text "Alex C" at 4180,2205 h60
